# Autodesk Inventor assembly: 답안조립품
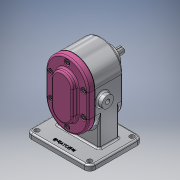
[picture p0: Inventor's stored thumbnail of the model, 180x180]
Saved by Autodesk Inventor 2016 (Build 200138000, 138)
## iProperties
Created: 2020-09
Part Number: 답안조립품
Material: 일반
Document SubType Name: Assembly
Designer: WIN7
Author: WIN7
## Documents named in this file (11)
- C:\Users\WIN7\Desktop\700906V1039\답안조립품.iam
- C:\Users\WIN7\Desktop\700906V1039\본체.ipt
- C:\Users\WIN7\Desktop\700906V1039\메인축.ipt
- C:\Users\WIN7\Desktop\700906V1039\서브축.ipt
- C:\Users\WIN7\Desktop\700906V1039\키 6 x 6 x 18.ipt
- C:\Users\WIN7\Desktop\700906V1039\베어링부시.ipt
- C:\Users\WIN7\Desktop\700906V1039\개스킷.ipt
- C:\Users\WIN7\Desktop\700906V1039\커버.ipt
- C:\Users\WIN7\Desktop\700906V1039\볼트 M5.ipt
- C:\Users\WIN7\Desktop\700906V1039\스퍼기어.ipt
- C:\Users\WIN7\Desktop\700906V1039\오일 실 16 28 7.ipt
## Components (1 placed, 1 different names)
1. 개스킷:1 — 플러쉬:1
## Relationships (1: Flush 1)
- 플러쉬:1 [Flush]: 개스킷:1
